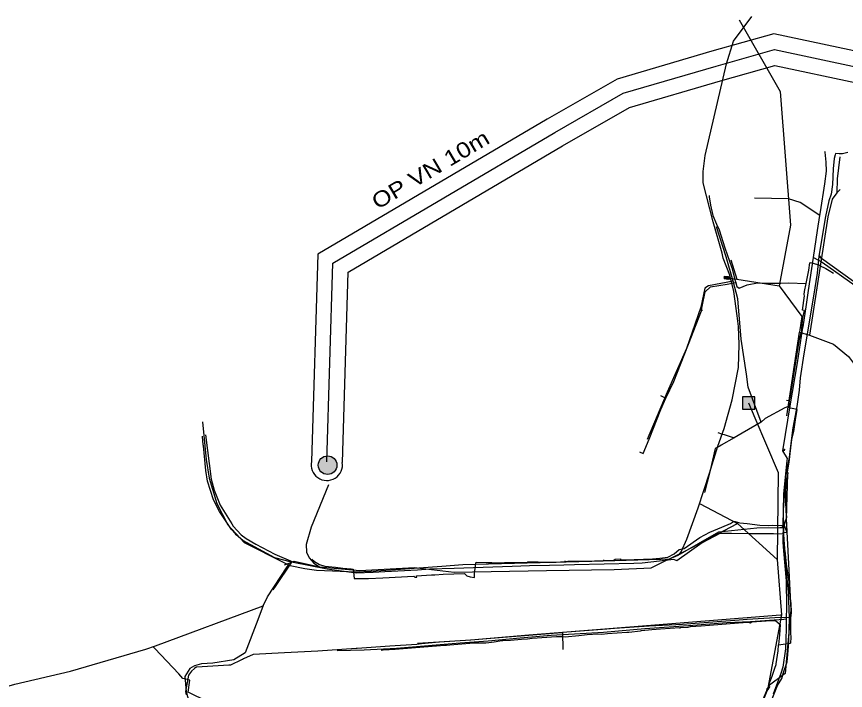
# Model space of a CAD drawing. Extents: x -589836 to -586542, y -1119607 to -1116793.
# Drawn here: x -589106 to -588569, y -1118200 to -1117764 of the extents above; entities that cross this region are included whole.
import ezdxf

# ---------------------------------------------------------------- set-up
doc = ezdxf.new("R2010")
doc.units = 0
doc.header["$LTSCALE"] = 4
doc.header["$PDMODE"] = 32
doc.header["$PDSIZE"] = 2
for name, color, linetype, lineweight in [('21', 7, 'Continuous', 25), ('22', 7, 'Continuous', 25), ('26', 7, 'Continuous', 25), ('29', 7, 'Continuous', 25), ('31', 7, 'Continuous', 25), ('39', 7, 'Continuous', 25), ('41', 7, 'Continuous', 25), ('53', 7, 'Continuous', 25)]:
    doc.layers.add(name, color=color, linetype=linetype, lineweight=lineweight)

msp = doc.modelspace()

# ---------------------------------------------------------------- hatches: boundary and pattern name
at = {"layer": '29'}
msp.add_hatch(color=256, dxfattribs=at).paths.add_polyline_path([(-588898.693, -1118054.489, 1), (-588910.768, -1118054.489, 1)])
at = {"layer": '39'}
msp.add_hatch(color=256, dxfattribs=at).paths.add_polyline_path([(-588635.805, -1118018.26), (-588627.805, -1118018.26), (-588627.805, -1118010.26), (-588635.805, -1118010.26)])

# ---------------------------------------------------------------- linework, layer by layer
at = {"layer": '21'}
msp.add_lwpolyline([(-588905.15, -1118052.338), (-588901.267, -1117923.545), (-588757.466, -1117838.815), (-588713.012, -1117813.46), (-588652.783, -1117795.811), (-588615.102, -1117785.14), (-588504.766, -1117808.551), (-588422.318, -1117870.318), (-588331.332, -1117935.642), (-588285.464, -1117969.199), (-588224.037, -1117990.567), (-588222.732, -1117991.024)], dxfattribs=at)
at = {"layer": '22'}
for points in [[(-588240.773, -1117974.158), (-588280.766, -1117960.245), (-588325.464, -1117927.545), (-588416.403, -1117862.254), (-588500.534, -1117799.226), (-588615.446, -1117774.844), (-588655.551, -1117786.202), (-588716.949, -1117804.193), (-588762.482, -1117830.164), (-588911.096, -1117917.73), (-588915.145, -1118052.037)], [(-588895.155, -1118052.639), (-588891.438, -1117929.36), (-588752.45, -1117847.466), (-588709.075, -1117822.727), (-588650.015, -1117805.42), (-588614.758, -1117795.436), (-588508.998, -1117817.876), (-588428.233, -1117878.382), (-588337.2, -1117943.739), (-588290.162, -1117978.153), (-588243.318, -1117994.447)]]:
    msp.add_lwpolyline(points, dxfattribs=at)
msp.add_arc((-588905.215, -1118054.252), 10.174, 167.42538, 9.10916, dxfattribs=at)
at = {"layer": '26'}
for p, q in [((-588640.47, -1117934.96), (-588640.16, -1117936.12)), ((-588662.27, -1117953.81), (-588661.68, -1117953.93)), ((-588688.93, -1118009.37), (-588685.38, -1118010.99)), ((-588607.18, -1118012.32), (-588605.22, -1118012.51)), ((-588608.67, -1118093.49), (-588607.03, -1118097.97)), ((-588789.37, -1118117.58), (-588775.62, -1118117.64)), ((-588750.93, -1118116.52), (-588750.91, -1118116.98)), ((-588725.87, -1118115.79), (-588725.86, -1118116.2)), ((-588676.38, -1118159.67), (-588676.34, -1118160.28)), ((-588791.69, -1118168.17), (-588791.15, -1118168.22)), ((-588869.99, -1118174.28), (-588868.79, -1118174.22)), ((-588620.17, -1118199.17), (-588619.12, -1118199.9))]:
    msp.add_line(p, q, dxfattribs=at)
for points in [[(-588657.29, -1117879.73), (-588657.43, -1117880.45), (-588656.53, -1117885.97), (-588655.06, -1117892.69), (-588652.69, -1117898.35), (-588650.79, -1117902), (-588647.28, -1117913.7), (-588642.63, -1117926.62), (-588640.47, -1117934.96)], [(-588594.41, -1117936.68), (-588592.81, -1117927.98), (-588592.03, -1117923.31), (-588591.69, -1117923.18), (-588586.27, -1117924.7), (-588585.92, -1117925.12), (-588581.66, -1117927.06), (-588579.64, -1117928.31), (-588576.7, -1117930.01)], [(-588662.27, -1117953.81), (-588661.84, -1117951.62), (-588659.99, -1117942.12), (-588656.59, -1117938.99), (-588645.68, -1117937.08), (-588640.16, -1117936.12)], [(-588640.16, -1117936.12), (-588640.1, -1117936.37), (-588639.41, -1117938.67), (-588637.82, -1117939.79), (-588632.81, -1117937.65), (-588625.99, -1117936.21), (-588622.15, -1117936.42), (-588617.92, -1117936.43), (-588610.91, -1117936.47), (-588606, -1117936.4), (-588594.41, -1117936.68)], [(-588605.22, -1118012.51), (-588604.87, -1118010.89), (-588601.06, -1117987.63), (-588600.63, -1117985.19), (-588600.05, -1117980.76), (-588598.69, -1117972.93), (-588597.74, -1117968.39), (-588597.27, -1117968.05), (-588597.19, -1117967.21), (-588597.35, -1117966.8), (-588597.11, -1117963.17), (-588596.58, -1117958.92), (-588595.55, -1117954.23), (-588596.95, -1117953.92), (-588595.64, -1117944.63), (-588595.83, -1117943.89), (-588595.48, -1117942.01), (-588594.41, -1117936.68)], [(-588685.38, -1118010.99), (-588680.25, -1118000.25), (-588670.69, -1117976.13), (-588662.4, -1117954.51), (-588662.27, -1117953.81)], [(-588702.48, -1118045.89), (-588700.06, -1118046.85), (-588696.3, -1118037.53), (-588688.74, -1118018.34), (-588685.38, -1118010.99)], [(-588608.67, -1118093.49), (-588606.9, -1118088.15), (-588607.43, -1118084.44), (-588607.56, -1118077.52), (-588607.74, -1118073.18), (-588607.43, -1118066.61), (-588606.24, -1118059.57), (-588606.49, -1118058.93), (-588605.53, -1118052.56), (-588604.31, -1118043.3), (-588603.86, -1118037.77), (-588602.42, -1118032.61), (-588601.47, -1118025.09), (-588600.27, -1118018.33), (-588605.71, -1118017.36), (-588605.22, -1118012.51)], [(-588706.01, -1118115.61), (-588694.07, -1118115.24), (-588689.34, -1118114.68), (-588684.11, -1118114.04), (-588679.98, -1118112.03), (-588676.83, -1118109.15), (-588673.64, -1118108.45), (-588663.41, -1118101.28), (-588656.82, -1118097.8), (-588649.1, -1118094.58), (-588643.45, -1118092.25), (-588641.63, -1118091.05), (-588640.4, -1118090.97), (-588638.33, -1118091.54), (-588637.37, -1118091.91), (-588632.77, -1118092.28), (-588624.41, -1118093.29), (-588618.88, -1118093.6), (-588616, -1118093.38), (-588608.67, -1118093.49)], [(-588608.23, -1118109.89), (-588609.38, -1118098.07), (-588607.03, -1118097.97)], [(-588607.03, -1118097.97), (-588607.01, -1118098.34), (-588606.8, -1118098.33)], [(-588608.23, -1118109.89), (-588607.41, -1118118.6), (-588606.17, -1118127.22), (-588605.83, -1118127.2)], [(-588915.02, -1118115.43), (-588913.23, -1118116.96), (-588910.03, -1118118.9), (-588906.56, -1118120), (-588899.67, -1118120.53), (-588894.74, -1118121.34), (-588889.42, -1118121.75), (-588888.2, -1118121.8), (-588887.55, -1118128.04), (-588878.27, -1118127.95), (-588868.89, -1118127.47), (-588848.79, -1118126.36), (-588848.26, -1118127.07), (-588846.84, -1118127.06), (-588847.1, -1118126.22), (-588837.35, -1118125.51), (-588835.26, -1118125.46), (-588829.76, -1118125.2)], [(-588829.76, -1118125.2), (-588815.87, -1118124.7), (-588814.35, -1118126.24), (-588812.38, -1118126.95), (-588809.58, -1118127.22), (-588809.49, -1118124.74), (-588808.53, -1118118.14), (-588808.38, -1118117.26), (-588801.98, -1118117.67), (-588798.28, -1118117.63), (-588792.17, -1118117.74), (-588790.13, -1118117.58), (-588789.37, -1118117.58)], [(-588775.62, -1118117.64), (-588774.91, -1118117.16), (-588768.2, -1118117.12), (-588766.06, -1118117.32), (-588758.83, -1118117.28)], [(-588758.83, -1118117.28), (-588756.57, -1118117.28), (-588750.91, -1118116.98)], [(-588750.91, -1118116.98), (-588749, -1118116.77), (-588745.1, -1118116.79)], [(-588745.1, -1118116.79), (-588737.48, -1118116.72), (-588725.86, -1118116.2)], [(-588725.86, -1118116.2), (-588719.1, -1118115.97), (-588718.31, -1118115.43), (-588714.81, -1118115.28), (-588714.8, -1118115.83), (-588709.99, -1118115.73), (-588706.01, -1118115.61)], [(-588605.83, -1118127.2), (-588605.45, -1118135.6), (-588604.31, -1118144.2), (-588604.17, -1118150.07), (-588604.54, -1118153.66), (-588604.7, -1118163.35), (-588604.5, -1118166.04), (-588604.56, -1118169.78)], [(-588676.38, -1118159.67), (-588670.86, -1118159.46), (-588669.51, -1118159.14), (-588662.49, -1118158.53), (-588646.36, -1118157.25), (-588638.23, -1118156.65), (-588632.39, -1118156.34), (-588630.8, -1118156.61), (-588629.6, -1118156.11), (-588617.25, -1118155.25), (-588614.05, -1118155.4), (-588611.41, -1118157.73), (-588611.85, -1118164.47), (-588612.31, -1118170.95)], [(-588710.72, -1118162.77), (-588709.44, -1118162.7), (-588701.85, -1118161.95), (-588701.2, -1118161.53), (-588694.61, -1118161.06), (-588688.8, -1118160.47), (-588676.38, -1118159.67)], [(-588791.15, -1118168.22), (-588786.2, -1118167.84), (-588778.94, -1118167.25), (-588775.02, -1118167.08), (-588772, -1118166.66), (-588756.32, -1118165.47)], [(-588756.32, -1118165.47), (-588756.02, -1118165.45), (-588752.58, -1118165.59)], [(-588752.58, -1118165.59), (-588750.62, -1118165.78), (-588741.85, -1118164.98), (-588736.43, -1118164.31), (-588729.39, -1118163.88), (-588727.01, -1118164.08), (-588723.25, -1118163.48), (-588710.72, -1118162.77)], [(-588868.79, -1118174.22), (-588861.02, -1118173.82), (-588850.4, -1118172.91), (-588828.62, -1118171.22)], [(-588828.62, -1118171.22), (-588828.02, -1118171.17), (-588827.99, -1118171.57)], [(-588828.02, -1118171.17), (-588809.97, -1118169.7), (-588802.08, -1118169.68), (-588800.12, -1118169.44)], [(-588800.12, -1118169.44), (-588796.78, -1118169.04), (-588791.69, -1118168.17), (-588791.66, -1118168.57)], [(-588614.02, -1118183.59), (-588613.94, -1118183.32), (-588612.54, -1118174.76), (-588612.31, -1118170.95), (-588604.56, -1118169.78)], [(-588619.12, -1118199.9), (-588618.13, -1118198.21), (-588618.67, -1118196.56), (-588616.46, -1118191.19), (-588614.71, -1118185.97), (-588614.02, -1118183.59)], [(-588625.64, -1118213.89), (-588623.68, -1118209.9), (-588621.05, -1118204.07), (-588619.72, -1118200.76), (-588619.12, -1118199.9)]]:
    msp.add_lwpolyline(points, dxfattribs=at)
at = {"layer": '29'}
msp.add_circle((-588904.73, -1118054.489), 6.037, dxfattribs=at)
at = {"layer": '31'}
for p, q in [((-588638, -1117765.75), (-588611.31, -1117812.22)), ((-588611.31, -1117812.22), (-588604.55, -1117898.85)), ((-588572.67, -1117854.54), (-588574.44, -1117868.94)), ((-588574.44, -1117868.94), (-588574.67, -1117878.02)), ((-588572.323, -1117875.721), (-588574.67, -1117878.02)), ((-588580.49, -1117893.51), (-588592.31, -1117970.16)), ((-588604.55, -1117898.85), (-588611.94, -1117938.25)), ((-588643.32, -1117921.3), (-588639.37, -1117934.02)), ((-588645.197, -1117934.107), (-588647.67, -1117933.742)), ((-588645.151, -1117933.798), (-588647.625, -1117933.433)), ((-588645.106, -1117933.489), (-588647.579, -1117933.124)), ((-588645.06, -1117933.18), (-588647.533, -1117932.815)), ((-588645.014, -1117932.871), (-588647.488, -1117932.506)), ((-588644.969, -1117932.562), (-588647.442, -1117932.197)), ((-588645.06, -1117933.18), (-588639.37, -1117934.02)), ((-588639.37, -1117934.02), (-588611.94, -1117938.25)), ((-588611.94, -1117938.25), (-588597.19, -1117958.08)), ((-588597.19, -1117958.08), (-588598.79, -1117968.24)), ((-588606.99, -1118022.44), (-588598.79, -1117968.24)), ((-588598.79, -1117968.24), (-588592.31, -1117970.16)), ((-588592.31, -1117970.16), (-588576.81, -1117976.13)), ((-588631.79, -1118014.15), (-588627.69, -1118023.89)), ((-588627.69, -1118023.89), (-588612.69, -1118059.2)), ((-588612.69, -1118059.2), (-588613.349, -1118115.611)), ((-588606.57, -1118060.17), (-588607.52, -1118089.29)), ((-588663.118, -1118079.579), (-588638.9, -1118092.18)), ((-588607.52, -1118089.29), (-588605.92, -1118118.35)), ((-588611.2, -1118151.47), (-588610.44, -1118151.45)), ((-588811.915, -1118167.65), (-588774.291, -1118164.478)), ((-588846.35, -1118169.949), (-588811.915, -1118167.65))]:
    msp.add_line(p, q, dxfattribs=at)
for points in [[(-588574.67, -1117878.02), (-588577.674, -1117881.966), (-588580.49, -1117893.51)], [(-588647.533, -1117932.815), (-588647.579, -1117933.124), (-588647.625, -1117933.433), (-588647.67, -1117933.742)], [(-588647.533, -1117932.815), (-588647.488, -1117932.506), (-588647.442, -1117932.197), (-588647.393, -1117931.867), (-588644.92, -1117932.232)], [(-588645.197, -1117934.107), (-588645.151, -1117933.798), (-588645.106, -1117933.489), (-588645.06, -1117933.18)], [(-588644.92, -1117932.232), (-588644.969, -1117932.562), (-588645.014, -1117932.871), (-588645.06, -1117933.18)], [(-588576.81, -1117976.13), (-588567.088, -1117984.106), (-588562.565, -1117990.089), (-588546.31, -1118017.42)], [(-588983.843, -1118034.742), (-588980.23, -1118063.63), (-588978.283, -1118070.731), (-588974.363, -1118080.458), (-588966.827, -1118092.552), (-588965.9, -1118094.023), (-588960.707, -1118099.661), (-588957.419, -1118102.057), (-588951.294, -1118105.71), (-588938.911, -1118112.215), (-588927.344, -1118117.135)], [(-588904.12, -1118067.19), (-588915.429, -1118094.615), (-588918.696, -1118105.855), (-588918.404, -1118110.868), (-588916.572, -1118114.527), (-588913.722, -1118117.968), (-588909.989, -1118120.436)], [(-588718.84, -1118122.15), (-588694.992, -1118120.944), (-588673.192, -1118110.313), (-588638.9, -1118092.18)], [(-588638.9, -1118092.18), (-588613.349, -1118115.611), (-588610.44, -1118151.45)], [(-588932.69, -1118119.11), (-588927.344, -1118117.135), (-588926.34, -1118116.78)], [(-588926.34, -1118116.78), (-588909.989, -1118120.436), (-588883.888, -1118122.64), (-588848.456, -1118120.752), (-588822.71, -1118123.81)], [(-588822.71, -1118123.81), (-588762.736, -1118122.724), (-588718.84, -1118122.15)], [(-588605.92, -1118118.35), (-588604.446, -1118148.269), (-588608.005, -1118189.464), (-588619.006, -1118197.757)], [(-588946.5, -1118145.372), (-588949.911, -1118154.636), (-588958.145, -1118176.216), (-588965.61, -1118180.653), (-588979.056, -1118182.859), (-588986.361, -1118183.328), (-588990.904, -1118184.572), (-588994.088, -1118186.182), (-588997.304, -1118191.395), (-588996.399, -1118201.089), (-588977.251, -1118273.873), (-588976.132, -1118295.656), (-588987.095, -1118343.851), (-588995.15, -1118386.44), (-588985.32, -1118402.35), (-588969.14, -1118406.59)], [(-588774.291, -1118164.478), (-588733.291, -1118161.208), (-588611.2, -1118151.47)], [(-588610.44, -1118151.45), (-588619.006, -1118197.757), (-588619.101, -1118198.162), (-588631.27, -1118227.16)]]:
    msp.add_lwpolyline(points, dxfattribs=at)
at = {"layer": '39'}
msp.add_lwpolyline([(-588635.805, -1118018.26), (-588627.805, -1118018.26), (-588627.805, -1118010.26), (-588635.805, -1118010.26)], close=True, dxfattribs=at)
msp.add_point((-588645.06, -1117933.18), dxfattribs=at)
at = {"layer": '41'}
for points in [[(-588676.585, -1118112.07), (-588675.539, -1118110.661), (-588671.855, -1118102.511), (-588664.582, -1118082.08), (-588657.181, -1118059.566), (-588651.785, -1118042.136), (-588647.727, -1118030.696), (-588642.497, -1118012.136), (-588638.31, -1117991.231), (-588637.86, -1117976.181), (-588638.415, -1117964.574), (-588639.252, -1117957.659), (-588641.394, -1117942.011), (-588643.99, -1117931.225), (-588648.309, -1117920.247), (-588648.853, -1117917.159), (-588654.792, -1117896.772), (-588661.176, -1117871.462), (-588661.257, -1117864.093), (-588659.939, -1117853.835), (-588646.043, -1117794.29), (-588641.586, -1117779.75), (-588629.635, -1117763.719)], [(-588567.35, -1117851.9), (-588571.02, -1117852.73), (-588571.21, -1117852.77), (-588573.01, -1117852.72), (-588575.54, -1117852.4), (-588575.57, -1117853.39), (-588576.329, -1117855.701), (-588577.04, -1117862.5), (-588577.36, -1117872.66), (-588578.22, -1117878.89), (-588579.84, -1117883.06), (-588581.9, -1117893.22), (-588586.24, -1117918.98), (-588587.39, -1117930.08), (-588589.78, -1117944.96), (-588595.97, -1117982.22), (-588598.32, -1117997.93), (-588598.96, -1118005.84), (-588600.56, -1118016.42), (-588603.09, -1118030.25), (-588605.35, -1118047.26), (-588605.54, -1118049.5), (-588607.86, -1118062.02), (-588609.4, -1118083.74), (-588609.606, -1118093.223), (-588609.62, -1118093.85), (-588609.97, -1118093.92), (-588609.898, -1118094.779)], [(-588536.089, -1117955.249), (-588584.62, -1117920.43), (-588585.28, -1117920.15), (-588585.1, -1117919.26), (-588585.96, -1117919.03), (-588586.24, -1117918.98)], [(-588985.921, -1118026.451), (-588983.412, -1118050.811), (-588981.565, -1118062.793), (-588976.561, -1118079.331), (-588969.301, -1118093.238), (-588958.861, -1118104.553), (-588932.595, -1118117.863), (-588928.966, -1118119.465), (-588919.451, -1118121.48), (-588911.984, -1118122.573), (-588886.135, -1118123.561), (-588876.557, -1118123.192), (-588857.37, -1118121.923), (-588830.61, -1118119.911), (-588816.985, -1118118.887), (-588733.402, -1118116.699), (-588688.581, -1118115.363), (-588683.052, -1118115.271), (-588677.535, -1118112.704), (-588651.188, -1118097.772), (-588626.544, -1118095.065), (-588611.46, -1118094.804), (-588609.367, -1118094.769)], [(-588609.367, -1118094.769), (-588609.497, -1118104.324), (-588609.248, -1118109.978), (-588607.504, -1118129.542), (-588607.323, -1118146.266), (-588607.409, -1118154.1), (-588607.336, -1118160.595), (-588607.852, -1118173.548), (-588609.647, -1118185.365), (-588610.9, -1118189.45), (-588612.946, -1118195.344), (-588615.967, -1118202.965)], [(-589423.803, -1118382.943), (-589416.6, -1118384.27), (-589392.15, -1118372.23), (-589375.08, -1118364.91), (-589350.82, -1118354.77), (-589334.88, -1118346.32), (-589323.33, -1118339.43), (-589221.4, -1118204.77), (-589188.05, -1118203.63), (-589146.37, -1118207.65), (-589107.53, -1118196.43), (-589071.34, -1118187.97), (-589022.64, -1118173.8), (-589016.193, -1118171.48), (-588946.566, -1118145.726), (-588943.705, -1118139.754), (-588930.933, -1118120.28), (-588930.16, -1118118.938)], [(-588898.579, -1118174.542), (-588881.009, -1118174.215), (-588859.953, -1118173.039), (-588818.861, -1118169.662), (-588800.66, -1118168.253), (-588779.943, -1118166.294), (-588759.73, -1118164.576), (-588725.771, -1118162.65), (-588699.05, -1118160.402), (-588670.756, -1118158.483), (-588645.823, -1118156.463), (-588630.538, -1118155.72), (-588608.962, -1118154.209), (-588607.409, -1118154.1)], [(-588946.455, -1118215.72), (-588971.951, -1118211.064), (-588982.743, -1118207.476), (-588989.958, -1118204.292), (-588995.036, -1118201.552), (-588994.116, -1118193.876), (-588998.566, -1118192.725), (-589001.121, -1118189.79), (-589016.617, -1118173.279), (-589017.3, -1118172.552), (-589017.46, -1118172.208), (-589017.515, -1118171.969)]]:
    msp.add_lwpolyline(points, dxfattribs=at)
at = {"layer": '53'}
for p, q in [((-588585.67, -1117892.69), (-588598.4, -1117884.13)), ((-588604.77, -1118015.91), (-588600.06, -1117988.13)), ((-588609.47, -1118043.93), (-588604.77, -1118015.91)), ((-588609.63, -1118044.92), (-588609.24, -1118044.99)), ((-588752.48, -1118163.03), (-588752.14, -1118173.96)), ((-588953.07, -1118177.29), (-588959.19, -1118180.08))]:
    msp.add_line(p, q, dxfattribs=at)
for points in [[(-588585.67, -1117892.69), (-588585.24, -1117890.35), (-588582.3, -1117872.12), (-588581.24, -1117863.95), (-588581.46, -1117857.98), (-588582.22, -1117851.69), (-588582.3, -1117851.07)], [(-588598.4, -1117884.13), (-588606.01, -1117881.95), (-588628.01, -1117881.33)], [(-588589.77, -1117919.87), (-588587.12, -1117902.3), (-588585.67, -1117892.69)], [(-588641.79, -1117935.2), (-588646.27, -1117919.46), (-588652.55, -1117900.05)], [(-588594.56, -1117951.89), (-588592.98, -1117941.34), (-588589.77, -1117919.87)], [(-588589.77, -1117919.87), (-588584.09, -1117922.85), (-588559.13, -1117940.58)], [(-588641.79, -1117935.2), (-588657.75, -1117938.18), (-588660.08, -1117939.8), (-588662.85, -1117951.96), (-588672.11, -1117978.93), (-588684.64, -1118007.11), (-588697.51, -1118037.89)], [(-588633.24, -1117995.41), (-588636.51, -1117972.8), (-588638.84, -1117946.69), (-588641.79, -1117935.2)], [(-588600.06, -1117988.13), (-588596.76, -1117966.58), (-588596.49, -1117964.8), (-588594.56, -1117951.89)], [(-588623.67, -1118026.63), (-588632, -1118003.95), (-588633.24, -1117995.41)], [(-588604.77, -1118015.91), (-588608.19, -1118017.36), (-588621.11, -1118024.21), (-588623.67, -1118026.63)], [(-588623.67, -1118026.63), (-588635.97, -1118033.79), (-588641.25, -1118036.8)], [(-588964.51, -1118098.96), (-588967.03, -1118096.28), (-588974.7, -1118084.57), (-588978.72, -1118077.04), (-588982.67, -1118064.8), (-588983.59, -1118057.92), (-588985.24, -1118042.04), (-588985.32, -1118041.23), (-588985.83, -1118035.88), (-588985.86, -1118035.58)], [(-588651.75, -1118033.28), (-588649.33, -1118034.09), (-588647.72, -1118034.63), (-588641.25, -1118036.8)], [(-588641.25, -1118036.8), (-588649.61, -1118041.56), (-588650.49, -1118042.06)], [(-588650.49, -1118042.06), (-588653.36, -1118043.71), (-588656.97, -1118058.76), (-588660.4, -1118072.27)], [(-588609, -1118076.38), (-588608.94, -1118073.28), (-588606.77, -1118051.45), (-588606.65, -1118050.26), (-588609.68, -1118045.2), (-588609.63, -1118044.92), (-588609.47, -1118043.93)], [(-588609.47, -1118043.93), (-588608.48, -1118044.1), (-588608.65, -1118045.09), (-588609.24, -1118044.99)], [(-588608.91, -1118099.23), (-588609.1, -1118081.04), (-588609, -1118076.38)], [(-588928.23, -1118117.43), (-588938.9, -1118114.62), (-588959.62, -1118103.31), (-588963.96, -1118099.55), (-588964.51, -1118098.96)], [(-588646.38, -1118098.79), (-588650.54, -1118098.81), (-588661.99, -1118104.92), (-588678.38, -1118116.58), (-588680.23, -1118115.7), (-588700.84, -1118118.03), (-588706.14, -1118118.16), (-588744.72, -1118119.12)], [(-588630.97, -1118098.88), (-588642.89, -1118098.78), (-588646.38, -1118098.79)], [(-588608.91, -1118099.23), (-588615.67, -1118099.02), (-588630.97, -1118098.88)], [(-588606.15, -1118134.63), (-588606.99, -1118125.71), (-588608.64, -1118102.93), (-588608.91, -1118099.23)], [(-588928.23, -1118117.43), (-588939.15, -1118133.67), (-588939.79, -1118134.62), (-588940.22, -1118135.26)], [(-588875.22, -1118124), (-588886.11, -1118124.47), (-588904.96, -1118121.78), (-588928.23, -1118117.43)], [(-588846.36, -1118122.44), (-588867.61, -1118123.67), (-588875.22, -1118124)], [(-588785.01, -1118120.18), (-588822.72, -1118121.38), (-588838.49, -1118121.98), (-588846.36, -1118122.44)], [(-588760.79, -1118119.51), (-588773.9, -1118119.82), (-588785.01, -1118120.18)], [(-588744.72, -1118119.12), (-588751.57, -1118119.29), (-588760.79, -1118119.51)], [(-588605.28, -1118153.42), (-588605.95, -1118136.76), (-588606.15, -1118134.63)], [(-588632.69, -1118154.56), (-588637.82, -1118154.88), (-588669.15, -1118157.26), (-588674.58, -1118157.67)], [(-588605.28, -1118153.42), (-588611.01, -1118153.21), (-588632.69, -1118154.56)], [(-588606.39, -1118177.2), (-588605.7, -1118169.48), (-588605.69, -1118169.01), (-588605.28, -1118153.42)], [(-588718.71, -1118160.33), (-588723.74, -1118160.68), (-588752.48, -1118163.03)], [(-588674.58, -1118157.67), (-588696.31, -1118158.78), (-588718.71, -1118160.33)], [(-588779.56, -1118165.35), (-588780.04, -1118165.39), (-588801.56, -1118167.13)], [(-588752.48, -1118163.03), (-588753.17, -1118163.09), (-588779.56, -1118165.35)], [(-588846.78, -1118170.76), (-588864.27, -1118171.73), (-588885.6, -1118173.33), (-588886.25, -1118173.37)], [(-588832.1, -1118169.22), (-588832.47, -1118169.24), (-588843.88, -1118170.18), (-588846.78, -1118170.76)], [(-588801.56, -1118167.13), (-588811.76, -1118167.96), (-588812.05, -1118167.98), (-588832.1, -1118169.22)], [(-588886.25, -1118173.37), (-588910.96, -1118174.95), (-588932.59, -1118176.17), (-588953.07, -1118177.29)], [(-588960.57, -1118180.71), (-588967.75, -1118184.04), (-588968.71, -1118184.09), (-588989.42, -1118185.36)], [(-588959.19, -1118180.08), (-588959.86, -1118180.38), (-588960.57, -1118180.71)], [(-588609.32, -1118189.56), (-588606.8, -1118181.86), (-588606.39, -1118177.2)], [(-588989.42, -1118185.36), (-588989.93, -1118185.31), (-588991.03, -1118186.33), (-588992.93, -1118188.09)], [(-588992.93, -1118188.09), (-588994.85, -1118190.57), (-588996.79, -1118201.17), (-588996.39, -1118203.36)], [(-588619.06, -1118211.81), (-588617.78, -1118209.15), (-588613.13, -1118197.37), (-588610.35, -1118192.71), (-588609.86, -1118191.21), (-588609.32, -1118189.56)]]:
    msp.add_lwpolyline(points, dxfattribs=at)

# ---------------------------------------------------------------- texts
at = {"layer": '22', "width": 1.2}
msp.add_text('OP VN 10m', height=10, rotation=30.688, dxfattribs=at).set_placement((-588872.33, -1117889.019))

doc.saveas('drawing.dxf')
